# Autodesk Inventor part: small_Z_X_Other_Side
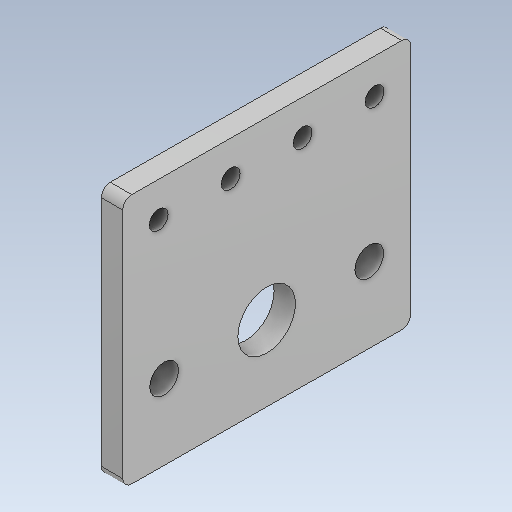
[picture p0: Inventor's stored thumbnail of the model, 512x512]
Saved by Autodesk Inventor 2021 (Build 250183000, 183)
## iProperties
Created: 2026-10
Part Number: small_Z_X_Other_Side
Material: Steel
Document SubType Name: Modeling
Designer: hp
Density: 7.85 g/cm^3
Appearance: Default
Author: hp
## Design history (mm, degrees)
feature "Body1"
body "Solid1"
